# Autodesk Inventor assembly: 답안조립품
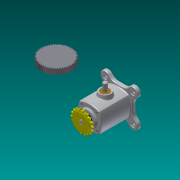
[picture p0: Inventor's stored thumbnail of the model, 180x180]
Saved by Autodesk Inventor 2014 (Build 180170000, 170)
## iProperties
Created: 2016-05
Part Number: 답안조립품
Document SubType Name: Assembly
Designer: Administrator
Author: Administrator
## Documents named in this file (12)
- C:\Users\Administrator\Desktop\460507V1018\답안조립품.iam
- C:\Users\Administrator\Desktop\460507V1018\본체.ipt
- C:\Users\Administrator\Desktop\460507V1018\M4x0.7x12.ipt
- C:\Users\Administrator\Desktop\460507V1018\베어링-6203.ipt
- C:\Users\Administrator\Desktop\460507V1018\부시.ipt
- C:\Users\Administrator\Desktop\460507V1018\스퍼기어.ipt
- C:\Users\Administrator\Desktop\460507V1018\스프로킷.ipt
- C:\Users\Administrator\Desktop\460507V1018\슬라이더.ipt
- C:\Users\Administrator\Desktop\460507V1018\오일실.ipt
- C:\Users\Administrator\Desktop\460507V1018\커버.ipt
- C:\Users\Administrator\Desktop\460507V1018\키5x5.ipt
- C:\Users\Administrator\Desktop\460507V1018\편심축.ipt
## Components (8 placed, 1 different names)
1. M4x0.7x12:2
2. M4x0.7x12:3
3. M4x0.7x12:4
4. M4x0.7x12:5
5. M4x0.7x12:1
6. M4x0.7x12:6
7. M4x0.7x12:7
8. M4x0.7x12:8
